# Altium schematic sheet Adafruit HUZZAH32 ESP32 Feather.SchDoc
size 282 x 200 mm; COMPANY: ADAFRUIT INDUSTRIES; DRAWN: KTOWN; REV: B
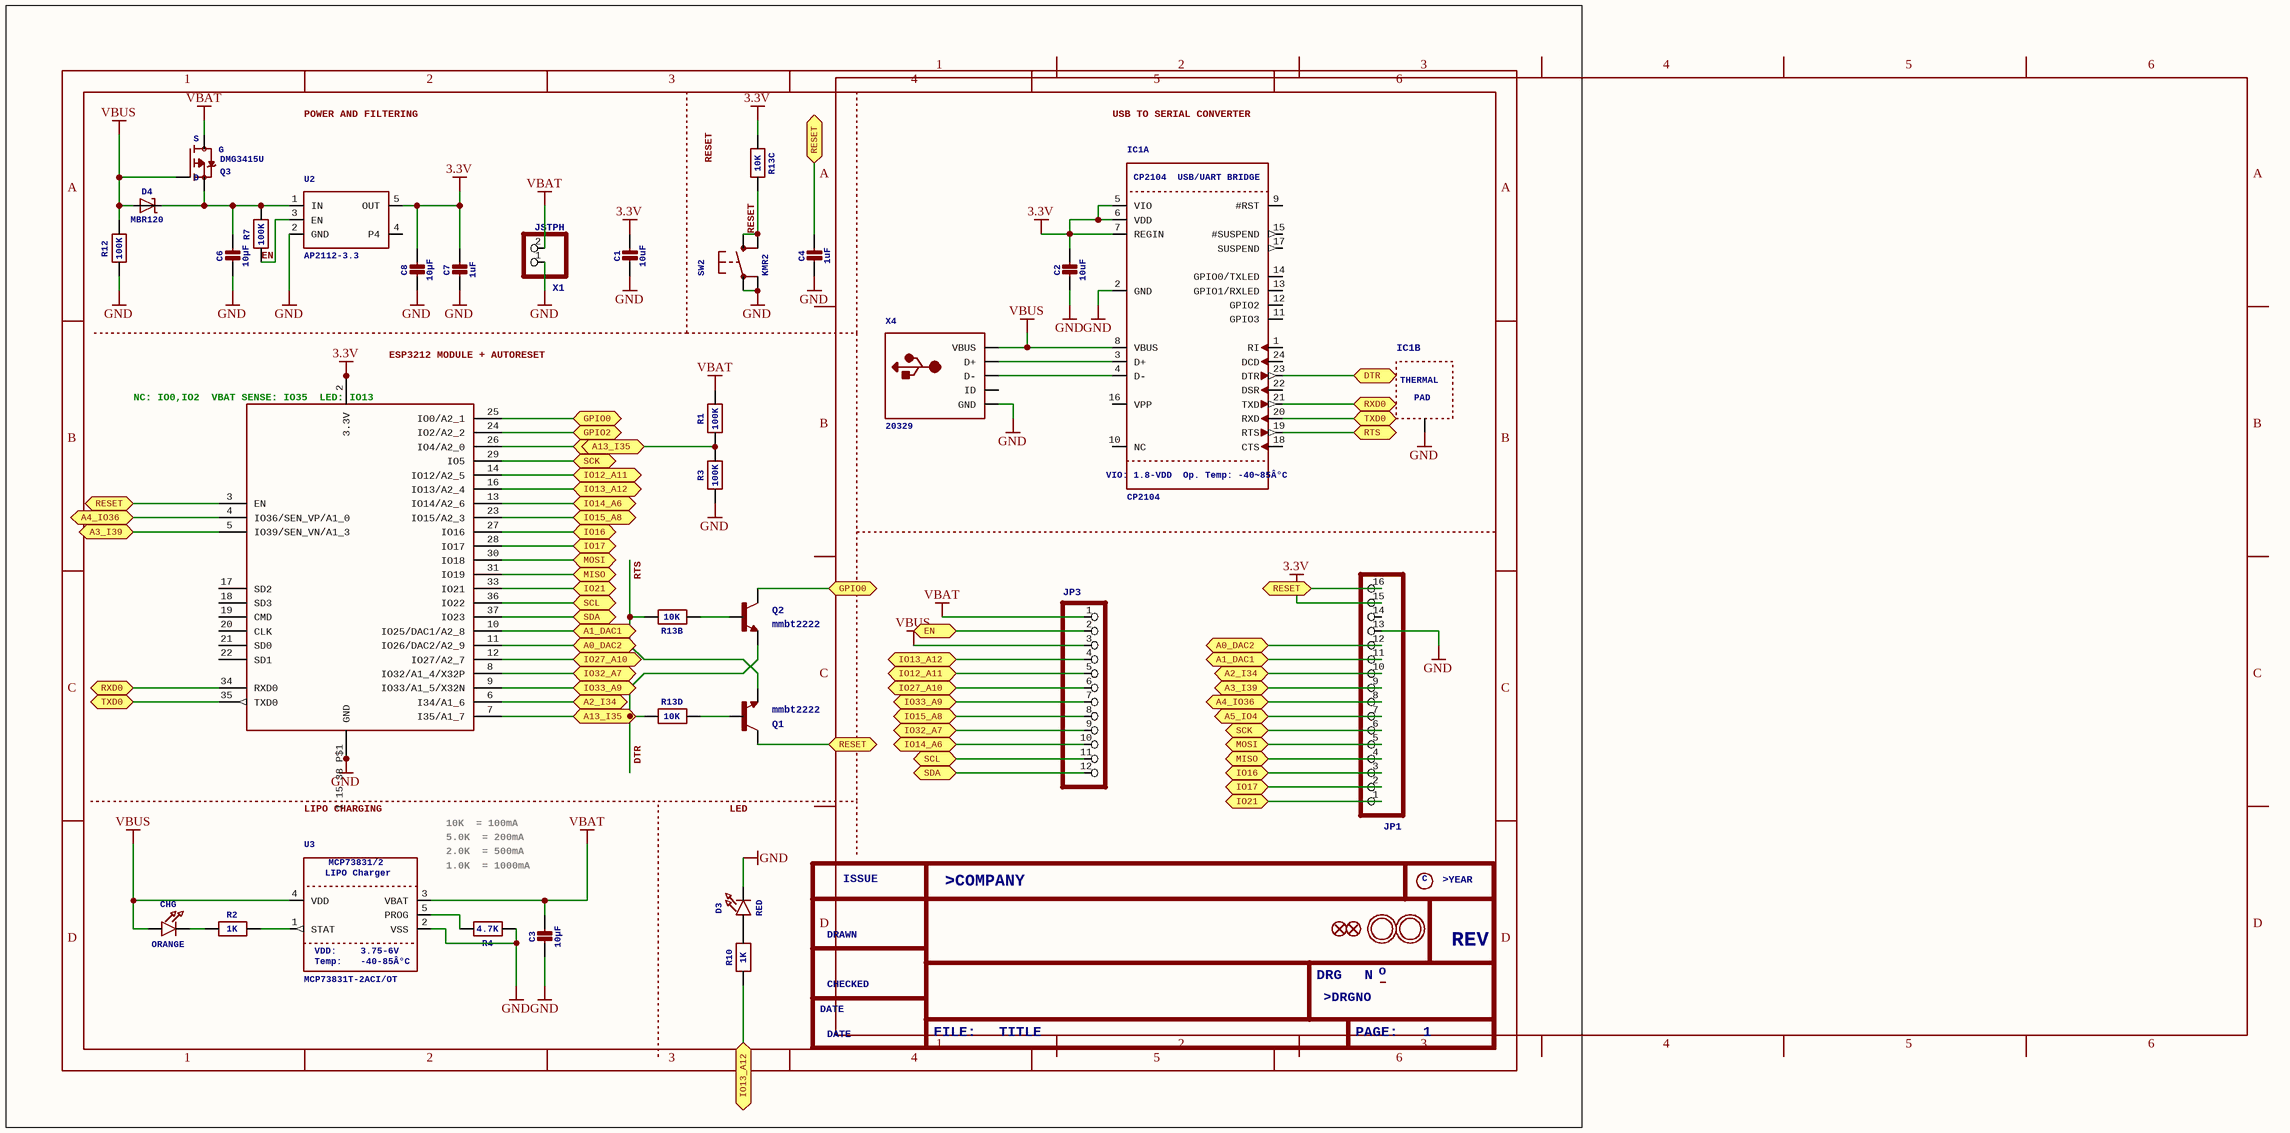
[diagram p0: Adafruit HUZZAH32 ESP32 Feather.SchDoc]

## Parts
C1  10uF  [0805-NO]
C2  10uF  [0805-NO]
C3  10µF  [0805-NO]
C4  1uF  [0603-NO]
C6  10µF  [0805-NO]
C7  1uF  [0603-NO]
C8  10µF  [0805-NO]
CHG  ORANGE  [CHIPLED_0805_NOOUTLINE]
D3  RED  [CHIPLED_0805_NOOUTLINE]
D4  MBR120  [SOD-123]
FRAME1  FRAME_A4  (value not drawn)  (parts A,B of 2)
IC1  CP2104  CP2104
USB/UARTBRIDGE: CP2104 / USB/UART BRIDGE  VIO:1.8-VDD
Op.Temp:-40~85Â°C: VIO: 1.8-VDD / Op. Temp: -40~85Â°C  [QFN24_4MM_SMSC]  (parts A,B of 2)
JP1  HEADER-1X16_MIN  [1X16_ROUND_MIN]  (value not drawn)
JP3  HEADER-1X12_MIN  [1X12_ROUND_MIN]  (value not drawn)
Q1  mmbt2222  [SOT23-3]
Q2  mmbt2222  [SOT23-3]
Q3  DMG3415U  [SOT23-R]
R1  100K  [0603-NO]
R2  1K  [0603-NO]
R3  100K  [0603-NO]
R4  4.7K  [0603-NO]
R7  100K  [0603-NO]
R10  1K  [0603-NO]
R12  100K  [0603-NO]
R13  10K  [RESPACK_4X0603]  (parts B,C,D of 4)
SW2  KMR2  [BTN_KMR2_4.6X2.8]
U2  AP2112-3.3  [SOT23-5]
U3  MCP73831T-2ACI/OT  LIPOCharger: LIPO Charger  Temp: Temp:  VDD: VDD:  [SOT23-5]
U$31  MOUNTINGHOLE2.5  [MOUNTINGHOLE_2.5_PLATED]  (value not drawn)
U$32  MOUNTINGHOLE2.5  [MOUNTINGHOLE_2.5_PLATED]  (value not drawn)
U$34  FIDUCIAL_1MM  [FIDUCIAL_1MM]  (value not drawn)
U$35  FIDUCIAL_1MM  [FIDUCIAL_1MM]  (value not drawn)
X1  JSTPH  [JSTPH2]
X2  ESP32_WROOM32_SKINNY  [WROOM32_SKINNY]  (value not drawn)
X4  20329  [4UCONN_20329_V2]

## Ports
A0_DAC2, A1_DAC1, A2_I34, A3_I39, A4_IO36, A5_IO4, A13_I35, DTR, EN, GPIO0, GPIO2, IO12_A11, IO13_A12, IO14_A6, IO15_A8, IO16, IO17, IO21, IO27_A10, IO32_A7, IO33_A9, MISO, MOSI, RESET, RTS, RXD0, SCK, SCL, SDA, TXD0

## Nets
3.3V: C1.1 C2.1 C7.1 C8.1 IC1.5(VIO) IC1.6(VDD) IC1.7(REGIN) JP1.15 R13.3 U2.5(OUT) X2.2(3.3V)
GND: C1.2 C2.2 C3.2 C4.2 C6.2 C7.2 C8.2 D3.C IC1.2(GND) IC1.THERM(TP) JP1.13 R3.1 R4.1 R12.1 SW2.A(P) SW2.A'(P1) U2.2(GND) U3.2(VSS) X1.1 X2.1_15_38_P$1(GND) X4.BASE@1_BASE@2_GND_SPRT@1_SPRT@2_SPRT@3_SPRT@4(GND)
VBAT: C3.1 JP3.1 Q3.3(D) R1.2 U3.3(VBAT) X1.2
VBUS: CHG.A D4.A IC1.8(VBUS) JP3.3 Q3.1(G) R12.2 U3.4(VDD) X4.VBUS
A0_DAC2: JP1.12 X2.11(IO26/DAC2/A2_9) ; port A0_DAC2
A1_DAC1: JP1.11 X2.10(IO25/DAC1/A2_8) ; port A1_DAC1
A2_I34: JP1.10 X2.6(I34/A1_6) ; port A2_I34
A3_I39: JP1.9 X2.5(IO39/SEN_VN/A1_3) ; port A3_I39
A4_IO36: JP1.8 X2.4(IO36/SEN_VP/A1_0) ; port A4_IO36
A5_IO4: JP1.7 X2.26(IO4/A2_0) ; port A5_IO4
DTR: Q2.2(E) R1.1 R3.2 R13.4 X2.7(I35/A1_7) ; port A13_I35
DTR: IC1.23(DTR) ; port DTR  [a separate net that carries the same name]
EN: R7.1 U2.3(EN)
EN: JP3.2 ; port EN  [a separate net that carries the same name]
GPIO0: Q2.3(C) X2.25(IO0/A2_1) ; port GPIO0
GPIO2: X2.24(IO2/A2_2) ; port GPIO2
IO12_A11: JP3.5 X2.14(IO12/A2_5) ; port IO12_A11
IO13_A12: JP3.4 R10.1 X2.16(IO13/A2_4) ; port IO13_A12
IO14_A6: JP3.10 X2.13(IO14/A2_6) ; port IO14_A6
IO15_A8: JP3.8 X2.23(IO15/A2_3) ; port IO15_A8
IO16: JP1.3 X2.27(IO16) ; port IO16
IO17: JP1.2 X2.28(IO17) ; port IO17
IO21: JP1.1 X2.33(IO21) ; port IO21
IO27_A10: JP3.6 X2.12(IO27/A2_7) ; port IO27_A10
IO32_A7: JP3.9 X2.8(IO32/A1_4/X32P) ; port IO32_A7
IO33_A9: JP3.7 X2.9(IO33/A1_5/X32N) ; port IO33_A9
MISO: JP1.4 X2.31(IO19) ; port MISO
MOSI: JP1.5 X2.30(IO18) ; port MOSI
RESET: C4.1 JP1.16 Q1.3(C) X2.3(EN) ; port RESET
RESET: R13.6 SW2.B(S) SW2.B'(S1)  [a separate net that carries the same name]
RTS: Q1.2(E) R13.7
RTS: IC1.19(RTS) ; port RTS  [a separate net that carries the same name]
RXD0: IC1.21(TXD) X2.34(RXD0) ; port RXD0
SCK: JP1.6 X2.29(IO5) ; port SCK
SCL: JP3.11 X2.36(IO22) ; port SCL
SDA: JP3.12 X2.37(IO23) ; port SDA
TXD0: IC1.20(RXD) X2.35(TXD0) ; port TXD0
NetC6_1: C6.1 D4.C Q3.2(S) R7.2 U2.1(IN)
NetCHG_C: CHG.C R2.1
NetD3_A: D3.A R10.2
NetIC1_3: IC1.3(D+) X4.D+
NetIC1_4: IC1.4(D-) X4.D-
NetQ1_1: Q1.1(B) R13.5
NetQ2_1: Q2.1(B) R13.2
NetR2_2: R2.2 U3.1(STAT)
NetR4_2: R4.2 U3.5(PROG)

Not connected (* = marked no-connect by the designer): IC1 1(RI) 9(#RST) 10(NC) 11(GPIO3) 12(GPIO2) 13(GPIO1/RXLED) 14(GPIO0/TXLED) 15(#SUSPEND) 16(VPP) 17(SUSPEND) 18(CTS) 22(DSR) 24(DCD); JP1 14; U2 4(P4); X2 17(SD2) 18(SD3) 19(CMD) 20(CLK) 21(SD0) 22(SD1); X4 ID

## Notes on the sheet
- POWER AND FILTERING
- (near R13) RESET
- USB TO SERIAL CONVERTER
- (near X2) ESP3212 MODULE + AUTORESET
- (near X2) NC: IO0,IO2
  VBAT SENSE: IO35
  LED: IO13
- LIPO CHARGING
- 10K  = 100mA
- 5.0K  = 200mA
- 2.0K  = 500mA
- 1.0K  = 1000mA
- LED

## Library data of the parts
C1-C3 C6 C8 = CAP_CERAMIC0805-NOOUTLINE: Ceramic Capacitors   For new designs, use the packages preceded by an '_' character since they are more reliable:   The following footprints should be used on most boards: _0402 - Standard footprint for regular board layouts  _0603 - Standard footprint for regular board layouts  _0805 - Standard footprint for regular board layouts  _1206 - Standard footprint for regular board layouts       For extremely tight-pitch boards where space is at a premium, the following 'micro-pitch' footprints can be used (smaller pads, no silkscreen outline, etc.): _0402MP - Micro-pitch footprint for very dense/compact boards  _0603MP - Micro-pitch footprint for very dense/compact boards  _0805MP - Micro-pitch footprint for very dense/compact boards  _1206MP - Micro-pitch footprint for very dense/compact boards
C4 C7 = CAP_CERAMIC0603_NO: Ceramic Capacitors   For new designs, use the packages preceded by an '_' character since they are more reliable:   The following footprints should be used on most boards: _0402 - Standard footprint for regular board layouts  _0603 - Standard footprint for regular board layouts  _0805 - Standard footprint for regular board layouts  _1206 - Standard footprint for regular board layouts       For extremely tight-pitch boards where space is at a premium, the following 'micro-pitch' footprints can be used (smaller pads, no silkscreen outline, etc.): _0402MP - Micro-pitch footprint for very dense/compact boards  _0603MP - Micro-pitch footprint for very dense/compact boards  _0805MP - Micro-pitch footprint for very dense/compact boards  _1206MP - Micro-pitch footprint for very dense/compact boards
CHG D3 = LED0805_NOOUTLINE: LED0603 - 0603 Surface Mount Package    2mA: Green LED - Low Power (3.9mcd, 2ma, 1.7Vf) - Digikey: 475-2709-2-ND  Orange LED - Low Power (9.8mcd, 2ma, 1.8Vf) - Digikey: 475-1194-2-ND  Red LED - Low Power (5mcd, 2ma, 1.8Vf) - Digikey: 475-1195-2-ND  Yellow LED - Low Power (7mcd, 2ma, 1.8Vf) - Digikey: 475-1196-2-ND       5mA: Blue LED - Low Power (17mcd, 5ma, 2.9Vf) - Digikey: LNJ937W8CRACT-ND    0805 - 0805 Surface Mount Package    2mA: Red LED (8.8mcd, 2mA, 1.8Vf, Clear) - Low Power [Digikey: 475-2510-1-ND]  Green LED (5mcd, 2mA, 1.8Vf, Clear) - Low Power [Digikey: 475-2730-1-ND]  Yellow LED (11.3mcd, 2mA, 1.8Vf, Clear) - Low Power [Digikey: 475-2555-1-ND]       20mA: Red LED (104mcd, 20mA, Diffused) - LS R976 [Digikey: 475-1278-6-ND]  Red LED (12mcd, 20mA, 2.0Vf, Clear) - APT2012EC [Digikey: 754-1128-1-ND]  Green LED (15mcd, 20mA, 2.2Vf, Clear) - APT2012GC [Digikey: 754-1131-1-ND]  Orange LED (160mcd, 20mA, 2.1Vf, Clear) - APT2012SECK [Digikey: 754-1130-1-ND]     1206 - 1206 Surface Mount Package  Green LED (26mcd, 20mA, Diffused) - LG N971  [Digikey: 475-1407-6-ND]  Red LED (15mcd, 20mA, Diffused) - LH N974 [Digikey: 475-1416-6-ND]     Cree - Cree High-Power Surface Mount LEDs  XPEBWT-L1-0000-00D50 - White 111lm 350mA 2.9Vf 6200K 110Â°  XTEAWT-00-0000-00000LEE3 - White 114lm 350mA 2.85Vf 5000K 115Â°     Everlight - Everlight 45-21 Series Surface Mount LEDs  45-21/QK2C-B2832AC2CB2/2T - Warm White 2000mcd 20mA 3.25Vf 3050K 120Â°  45-21/LK2C-B38452C4CB2/2T - Nuetral White 2000mcd 20mA 3.25Vf 4150K 120Â°  45-21/LK2C-B50634C6CB2/2T - Cold White 2200mcd 20mA 3.25Vf 5650K 120Â°     PLCC2 Reverse Mount LS T77K-J1L2-1-0-2-R18-Z - Red 11.25mcd 2mA 1.8Vf 630nm 120Â°  LO T77K-L1M2-24-Z - Orange 19.6mcd 2mA 1.8Vf 606nm 120Â°  LY T77K-K2M1-26-Z - Yellow 15.7mcd 2mA 1.8Vf 587nm 120Â°
D4 = DIODE-SCHOTTKYSOD-123
FRAME1 = FRAME_A4: FRAME   DIN A4, landscape with location and doc. field
IC1 = CP2104: CP2104 - USB to UART Bridge    VDD Output: 3.45V
JP1 = HEADER-1X16_MIN: PIN HEADER
Q1 Q2 = TRANSISTOR_NPNSOT23-3: Transistor NPNBJT configuration in SOT23 package. MMBT2222 is the common NPN we use. Double check BCE configuration again layout.
Q3 = MOSFET-P: P-Channel Mosfet   LEGEND   VDS: Voltage Drain-Source ID: Drain Current RDS(ON): Drain-Source On-State Resistance VGS(TH): Gate-Source Threshold Voltage CISS: Drain-Source Input Capacitance    SOT-23   Name	VDS	ID	RDS(ON)	VGS(TH)	CISS	Order Number	   IRLML5103	30V	760mA	600 mOhm	--	75pF @ 25V	Digikey: IRLML5103PBFCT-ND	   IRLML6401	12V	4.3A	50 mOhm	950mV @ 250ÂµA	830pF @ 10V	Digikey: IRLML6401PBFTR-ND	   NTR0202PL	20V	400mA	800 mOhm	2.3V @ 250uA	70pF @ 5V	Digikey: NTR0202PLT1GOSTR-ND	   NTR4101PT1G	20V	1.8A	85 mOhm	1.2V @ 250uA	675pF @ 10V	Digikey: NTR4101PT1GOSCT-ND	   DMP2004K	20V	600mA	900 mOhm	1V @ 250uA	175pF @ 16V	Digikey: DMP2004KDICT-ND	   PMV65XP	20V	3.9A	76 mOhm	950mV @ 1mA	725pF @ 20V	Digikey: 568-2358-2-ND	   							   							TO-252   Name	VDS	ID	RDS(ON)	VGS(TH)	CISS	Order Number	   AOD417	30V	25A	34 mOhm	3V @ 250ÂµA	920pF @ 15V	Digikey: 785-1106-2-ND	PowerPak   Name	VDS	ID	RDS(ON)	VGS(TH)	CISS	Order Number	   AON7401	30V	12A	14 mOhm	3V @ 250ÂµA	2600pF @ 15V	Digikey: 785-1302-1-ND
R1-R4 R7 R10 R12 = RESISTOR_0603_NOOUT: Resistors   For new designs, use the packages preceded by an '_' character since they are more reliable:   The following footprints should be used on most boards: _0402 - Standard footprint for regular board layouts  _0603 - Standard footprint for regular board layouts  _0805 - Standard footprint for regular board layouts  _1206 - Standard footprint for regular board layouts       For extremely tight-pitch boards where space is at a premium, the following 'micro-pitch' footprints can be used (smaller pads, no silkscreen outline, etc.): _0402MP - Micro-pitch footprint for very dense/compact boards  _0603MP - Micro-pitch footprint for very dense/compact boards  _0805MP - Micro-pitch footprint for very dense/compact boards  _1206MP - Micro-pitch footprint for very dense/compact boards
R13 = RESISTOR_4PACK: Resistor Packs (4 resistors)   4 x 0603 10K 1/16W - Digikey: YC164J-10KCT-ND
SW2 = SWITCH_TACT_SMT4.6X2.8: SMT Tact Switches 6x6mm - Digikey: P12940SCT-ND  KMR2 (4.6x2.8mm) - Digikey: 401-1426-1-ND  EVQ-PQHB55 - Light Touch, 160GF (4.5x4.5mm) - Digikey: P8090SCT-ND  KMT0 - KMT021 NGJ LHS (etc.) IP68/Waterproof - Digikey: CKN10289CT-ND
U2 = VREG_SOT23-5: SOT23-5 Fixed Voltage Regulators      Part	Current Out	V Out	V In	V Dropout	Î¸JA (Â°C/W)	TJ (Â°C)	Digikey Part No.	     ADP121	  150mA	  3.3V	  3.4-5.5V	  0.09V @ 150mA	  --	  --	  ADP121-AUJZ33R7CT-ND	     ADP121	  150mA	  3.0V	  3.1-5.5V	  0.09V @ 150mA	  --	  --	  ADP121-AUJZ30R7CT-ND	     ADP122	  300mA	  3.3V	  3.4-5.5V	  0.085V @ 300mA	  --	  --	  ADP122AUJZ-3.3-R7CT-ND	     ADP1712	  300mA	  3.3V	  3.5-5.5V	  0.17V @ 300mA	  --	  --	  ADP1712AUJZ-3.3-R7TR-ND	     AP7311 (Low Cost)	  150mA	  3.3V	  3.5-6V	  0.15V @ 150mA	  --	  --	  AP7311-33WG-7DICT-ND	     LD39015M18R	  150mA	  1.8V	  1.9V-5.5V	  0.08V @ 100mA	  --	  --	  497-6977-1-ND	     LP2985A-33DBVR	  150mA	  3.3V	  3.3-16V	  0.28V @ 150mA	  206	  150	  296-18479-1-ND	     MCP1824T-3302E/OT	  300mA	  3.3V	  3.5V-6V	  0.2V @ 300mA	  --	  --	  MCP1824T-3302E/OTCT-ND	     MIC5205-2.5YM5 TR	  150mA	  2.5V	  2.7-16V	  0.165V @ 150mA	  --	  --	  576-1257-2-ND	     MIC5205-3.0YM5 TR	  150mA	  3.0V	  3.2V-16V	  0.165V @ 150mA	  --	  --	  576-1258-2-ND	     MIC5205-3.3YM5 TR	  150mA	  3.3V	  3.5V-16V	  0.165V @ 150mA	  --	  --	  576-1259-2-ND	     TPS780330220	  150mA	  3.3V+2.2V	  3.6-5.5V	  250mV Max	  --	  --	  296-23332-1-ND	     TDA3663/N1,135	  100mA	  3.3V	  3.5-45V	  0.18V @ 50mA	  --	  --	  568-5343-1-ND	     	  	  	  	  	  	  	  	     	  	  	  	  	  	  	  	   Max operating temp can be calculated using Î¸JA, TJ (max junction temperature), and power in watts.  Set the "Maximum Ambient Temperature" until it reaches TJ ("Max Junction Temperature"), which is the absolute limit for safe use of the regulator: Heat Sink Temperature Calculator   For example, With 12V source into a 3.3V LP2985 and a 30mA load, we are dissipating (12V-3.3V) * 0.03A = 0.261W.  With a Î¸JA of 206 Â°C/W, a TJ of 150Â°C, and 261mW we can safely use the chip without a heat sink up to 75Â°C (=147.1Â°C Junction Temperature).
U3 = MCP73831/2: MCP73831/2 LIPO Charger    VDD: 3.75 - 6V  Temp -40 - 85Â°C  Programmable Charge Rate: 15-500mA       NOTE: STAT is a tri-state logic output on the MCP73831 and an open-drain output on the MCP73832.   SOT23-5 with 4.2V output and tri-state logic on STAT = MCP73831T-2ACI/OT
U$31 U$32 = MOUNTINGHOLE2.5: Mounting Hole   For #2 screws (0.086"/2.18mm width, 0.094"/2.4mm hole) use 2.5mm; BOM: EXCLUDE
U$34 U$35 = FIDUCIAL_1MM: Fiducial Alignment Points   Various fiducial points for machine vision alignment.; BOM: EXCLUDE
X1 = CON_JST_PH_2PIN: JST 2-Pin Right-Angle Connector  PH-Series - 4UConnector: 17311  SH-Series - 4UConnector: 07278
X4 = USB_MICRO_20329_V2: USB ConnectorsUSBMINIB - Surface Mount Female Mini-B USB Connector    4UConnector: 06564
